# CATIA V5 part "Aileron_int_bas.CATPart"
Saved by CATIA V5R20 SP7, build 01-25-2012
Part number: Aileron_int_bas
Bounding box of the stored display mesh (mm): x -250 to 250, y -11.378 to 81.693, z 84.573 to 119.235
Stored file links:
  F:\Travaux\Modélisations\CFAO_2011\MMS\MMS_GR2\AA_OK\tquattrone\Catia\Aileron_int_bas.CATPart
  C:\Users\Tom\Documents\Cours 2A\CFAO\Projet thinkmotion\Aileron_citroen.CATProduct
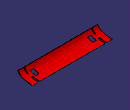
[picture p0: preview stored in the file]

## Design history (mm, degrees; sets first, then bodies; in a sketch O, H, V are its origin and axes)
Parameters
  Epaisseur_trou_extension = 5 mm
  epaisseur_trou_verin = 10.75 mm
Set1
  Plane1 "Plan_bout": linked copy from another document
  Plane2 "Plan_sym": linked copy from another document
  Plane3 "Plan_bielle2/3": linked copy from another document
  Plane4 "Plan_verin": linked copy from another document
Body1 (main body)
  Sketch1 on Plane1, origin (250, 0, 0), H (0, 1, 0), V (0, 0, 1)
    spline S1 through (-11.3778, 118.6731) (-7.2781, 112.9278) (4.6988, 100.2242) (19.5573, 93.0165) (38.1081, 88.0612) (66.6545, 84.6376) (81.6932, 84.6376)
    spline S2 through (81.6932, 84.6376) (69.8063, 85.6286) (55.9383, 87.1602) (20.3174, 94.4132) (10.7834, 98.6226) (-7.7516, 116.6326) (-9.6899, 119.2354)
    line L1 (-11.3778, 118.6731) -> (-9.6899, 119.2354)
    point P1 (-11.3778, 118.6731)
    point P2 (-9.6899, 119.2354)
    point P3 (81.6932, 84.6376)
    point P4 (81.6932, 84.6376)
    point P5 (-11.3778, 118.6731)
    point P6 (-9.6899, 119.2354)
    coincidence: P3 P4, P5 P1, P6 P2
  Pad1: profile Sketch1, direction (-1, 0, 0), up to Plane2
  Sketch2 on Plane3, origin (210, 0, 0), H (0, 1, 0), V (0, 0, 1)
    line L1 (84.9612, 85.6002) -> (36.9747, 93.2172)
    line L2 (36.9747, 93.2172) -> (35.877, 86.3015)
    line L3 (35.877, 86.3015) -> (83.8634, 78.6845)
    line L4 (83.8634, 78.6845) -> (84.9612, 85.6002)
    parallelism: L4 L2, L1 L3
    perpendicularity: L1 L2
  Pocket1: profile Sketch2, direction (-1, 0, 0), length 5 {= Epaisseur_trou_extension}, mirrored extent
  Sketch3 on Plane3, origin (210, 0, 0), H (0, 1, 0), V (0, 0, 1)
    line L1 (-12.0902, 114.2322) -> (-1.5543, 123.7039)
    line L2 (-1.5543, 123.7039) -> (20.2344, 99.4671)
    line L3 (20.2344, 99.4671) -> (9.6986, 89.9954)
    line L4 (9.6986, 89.9954) -> (-12.0902, 114.2322)
    parallelism: L4 L2, L1 L3
    perpendicularity: L1 L2
  Pocket2: profile Sketch3, direction (1, 0, 0), length 5 {= Epaisseur_trou_extension}
  Sketch4 on Plane4, origin (180, 0, 0), H (0, 1, 0), V (0, 0, 1)
    line L1 (42.208, 89.826) -> (37.9423, 81.5847)
    line L2 (37.9423, 81.5847) -> (6.9244, 97.6397)
    line L3 (6.9244, 97.6397) -> (11.19, 105.8809)
    line L4 (11.19, 105.8809) -> (42.208, 89.826)
    parallelism: L4 L2, L1 L3
    perpendicularity: L1 L2
  Pocket3: profile Sketch4, direction (-1, 0, 0), length 10.75 {= epaisseur_trou_verin}, mirrored extent
  Mirror1: of the body so far, about Plane2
